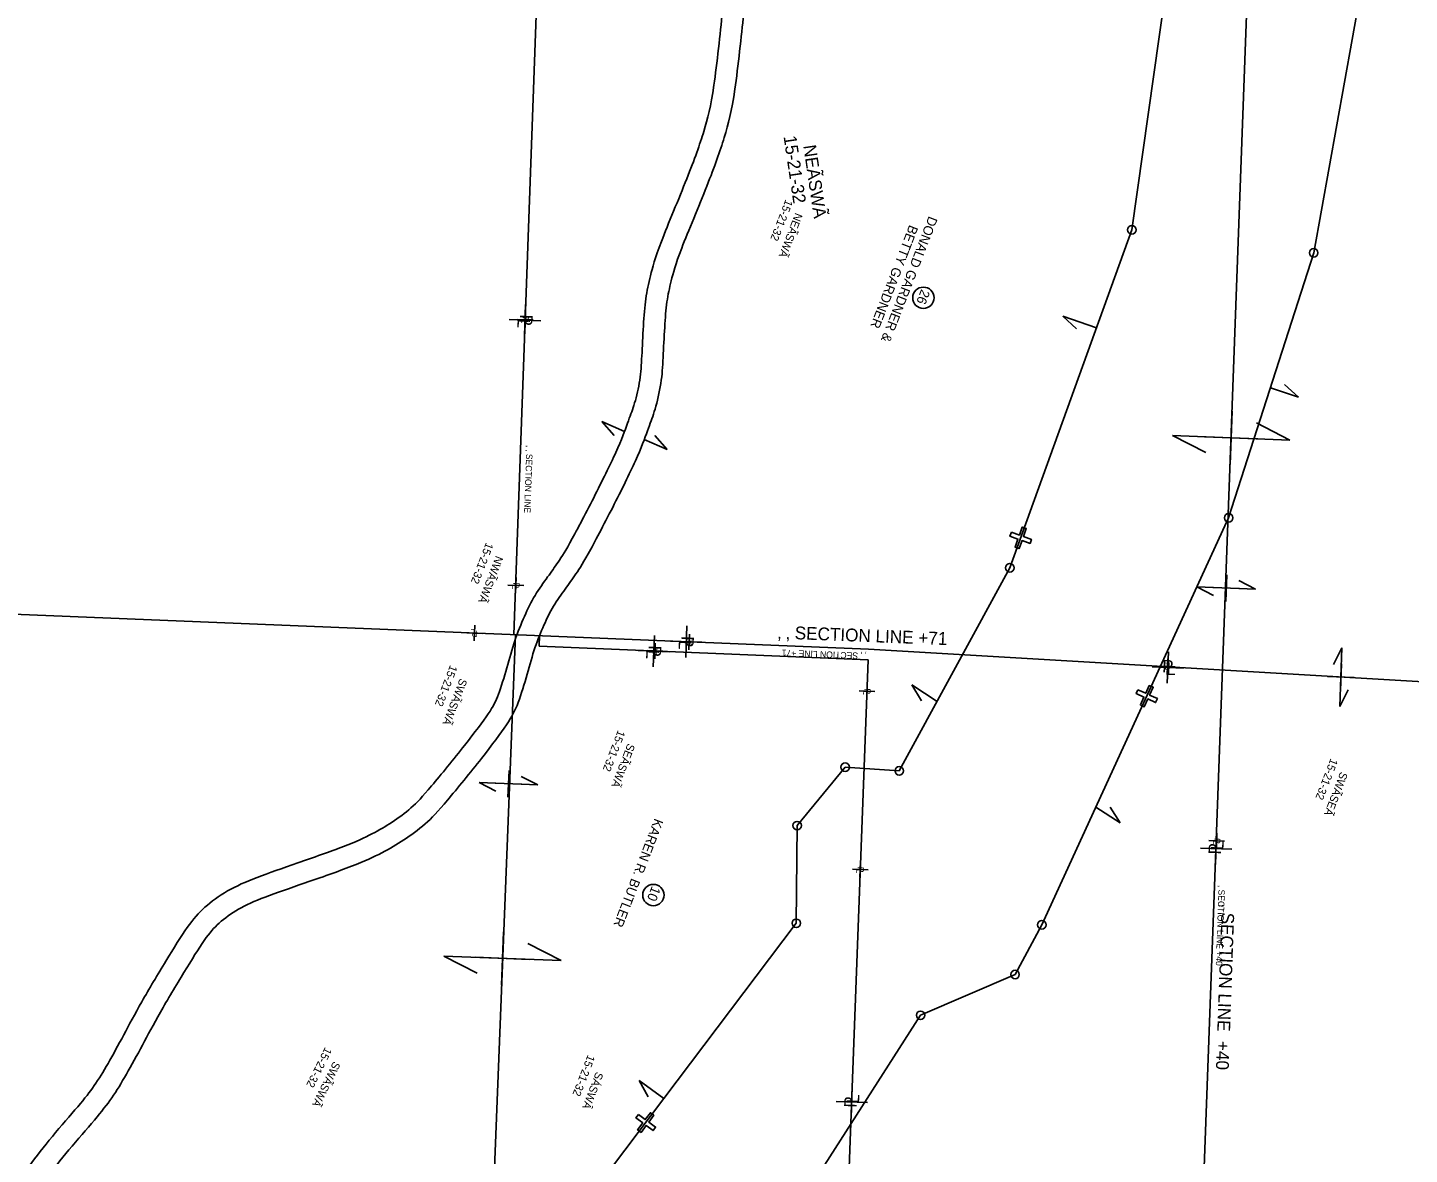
# Model space of a CAD drawing. Extents: x 2814293 to 2835768, y 121185 to 156337.
# Drawn here: x 2821316 to 2823907, y 136651 to 138763 of the extents above; entities that cross this region are included whole.
import ezdxf

# ---------------------------------------------------------------- set-up
doc = ezdxf.new("R2010")
doc.units = 0
for name, color, linetype in [('Photo-Retaining wall', 7, 'Continuous'), ('Roadway-Alignment notes', 7, 'Continuous'), ('Roadway-Ditches', 7, 'Continuous'), ('Roadway-Edge of pavement', 7, 'Continuous'), ('Roadway-Edge of shoulder', 7, 'Continuous'), ('Roadway-Entrances', 7, 'Continuous'), ('Roadway-New rw', 7, 'Continuous'), ('Roadway-Safety', 7, 'Continuous'), ('Roadway-Walls', 7, 'Continuous'), ('Scratch-2', 7, 'Continuous'), ('Scratch-5', 7, 'Continuous'), ('Text-New rw label', 7, 'Continuous'), ('Traffic_Control-Traffic barriers', 7, 'Continuous')]:
    doc.layers.add(name, color=color, linetype=linetype)

msp = doc.modelspace()

# ---------------------------------------------------------------- linework, layer by layer
at = {"layer": 'Roadway-Ditches'}
for centre in [(2822996, 138256.8), (2822489.8, 137137)]:
    msp.add_circle(centre, 20, dxfattribs=at)
at = {"layer": 'Roadway-Edge of pavement'}
for p, q in [((2822416.1, 137998.8), (2822392.8, 138025)), ((2822392.8, 138025), (2822435.6, 138006.4)), ((2822472.6, 137991), (2822515.4, 137972.4)), ((2822492.2, 137998.6), (2822515.4, 137972.4)), ((2823564.7, 137737.7), (2823562.7, 137687.7)), ((2823587.5, 137726.6), (2823618.7, 137710.6)), ((2823618.7, 137710.6), (2823508.7, 137714.8)), ((2823539.9, 137698.8), (2823508.7, 137714.8)), ((2823538.7, 137713.7), (2823588.7, 137711.7)), ((2823563.7, 137712.7), (2823563.7, 137712.7)), ((2823764.8, 137569.6), (2823780.8, 137600.7)), ((2823776.5, 137490.8), (2823780.8, 137600.7)), ((2823779.6, 137570.7), (2823777.7, 137520.7)), ((2823803.6, 137544.8), (2823753.6, 137546.7)), ((2823778.6, 137545.7), (2823778.6, 137545.7)), ((2823792.5, 137521.9), (2823776.5, 137490.8)), ((2822217.1, 137320.7), (2822219.1, 137370.7)), ((2822241.9, 137359.5), (2822273.1, 137343.5)), ((2822163.1, 137347.8), (2822273.1, 137343.5)), ((2822194.3, 137331.8), (2822163.1, 137347.8)), ((2822243.1, 137344.7), (2822193.1, 137346.6)), ((2822218.1, 137345.7), (2822218.1, 137345.7))]:
    msp.add_line(p, q, dxfattribs=at)
at = {"layer": 'Roadway-Edge of shoulder'}
for p, q in [((2822250.1, 138244.3), (2822248, 138185.4)), ((2822278.5, 138213.8), (2822219.6, 138215.9)), ((2822491.5, 137623.8), (2822489.4, 137564.9)), ((2822552.4, 137641.5), (2822550.4, 137582.6)), ((2822519.9, 137593.3), (2822461, 137595.4)), ((2822580.8, 137611), (2822522, 137613.1)), ((2823455.4, 137593.2), (2823453.3, 137534.3)), ((2823424.9, 137564.8), (2823483.8, 137562.7)), ((2823543.6, 137194.4), (2823545.6, 137253.3)), ((2823515.2, 137224.9), (2823574.1, 137222.8)), ((2822860.5, 136719.6), (2822862.5, 136778.5)), ((2822832.1, 136750.1), (2822891, 136748))]:
    msp.add_line(p, q, dxfattribs=at)
at = {"layer": 'Roadway-Entrances'}
for p, q in [((2822275.4, 138939.5), (2822227.8, 137625.4)), ((2823507.8, 136237.3), (2823605.3, 138881.7)), ((2823257.6, 138222.3), (2823320.5, 138200.6)), ((2823283.3, 138198.6), (2823257.6, 138222.3)), ((2823646.5, 138087.9), (2823699.1, 138070.8)), ((2823699.1, 138070.8), (2823673, 138094)), ((2820897, 137680), (2822893.1, 137598.2)), ((2822231.2, 137625.3), (2822073.3, 133645.3)), ((2822893.1, 137598.2), (2824874.2, 137481)), ((2823021.5, 137499.8), (2822974.1, 137530.9)), ((2822992.6, 137501.1), (2822974.1, 137530.9)), ((2823020.1, 137500.7), (2823020.1, 137500.7)), ((2823364.7, 137272.4), (2823319.3, 137302.1)), ((2823346.2, 137302.1), (2823364.7, 137272.4)), ((2822509.3, 136755.7), (2822463.2, 136789.4)), ((2822480.1, 136758.7), (2822463.2, 136789.4)), ((2822507.6, 136756.9), (2822507.6, 136756.9))]:
    msp.add_line(p, q, dxfattribs=at)
at = {"layer": 'Roadway-New rw'}
for p, q in [((2823500.4, 139189.9), (2823386.8, 138384.2)), ((2823727.7, 138341.1), (2823819.8, 138853.3)), ((2823386.8, 138384.2), (2823158, 137750.7)), ((2823568.3, 137844.4), (2823727.7, 138341.1)), ((2823218, 137081.4), (2823568.3, 137844.4)), ((2823158, 137750.7), (2822950.8, 137369.8)), ((2822849.2, 137376.9), (2822759.1, 137267.2)), ((2822950.8, 137369.8), (2822849.2, 137376.9)), ((2822759.1, 137267.2), (2822757.7, 137084.1)), ((2822757.7, 137084.1), (2822189.2, 136332.5)), ((2823167.8, 136988), (2823218, 137081.4)), ((2823167.8, 136988), (2822990.8, 136911.6))]:
    msp.add_line(p, q, dxfattribs=at)
for points in [[(2823160.9, 137817.3), (2823158.3, 137809.8), (2823173.3, 137804.4), (2823168, 137789.4), (2823175.5, 137786.7), (2823180.9, 137801.7), (2823195.9, 137796.4), (2823198.6, 137803.9), (2823183.6, 137809.3), (2823188.9, 137824.3), (2823181.4, 137827), (2823176, 137812), (2823160.9, 137817.3)], [(2823398.3, 137522), (2823395, 137514.8), (2823409.5, 137508.1), (2823402.8, 137493.6), (2823410.1, 137490.2), (2823416.8, 137504.7), (2823431.3, 137498), (2823434.6, 137505.3), (2823420.1, 137512), (2823426.8, 137526.5), (2823419.5, 137529.9), (2823412.8, 137515.3), (2823398.3, 137522)], [(2822461.7, 136725.8), (2822456.9, 136719.4), (2822469.7, 136709.8), (2822460.2, 136697), (2822466.6, 136692.2), (2822476.1, 136705), (2822489, 136695.5), (2822493.8, 136701.9), (2822480.9, 136711.4), (2822490.5, 136724.3), (2822484.1, 136729), (2822474.5, 136716.2), (2822461.7, 136725.8)]]:
    msp.add_lwpolyline(points, close=True, dxfattribs=at)
msp.add_lwpolyline([(2822670.7, 136411.7), (2822990.8, 136911.6)], dxfattribs=at)
at = {"layer": 'Roadway-Walls'}
for p, q in [((2822264.2, 138215.4), (2822234.8, 138216.4)), ((2822250, 138230.6), (2822249, 138201.2)), ((2822232.3, 137732.5), (2822231.2, 137703)), ((2822246.5, 137717.2), (2822217, 137718.3)), ((2822153.9, 137613.5), (2822154.9, 137642.9)), ((2822169.1, 137627.7), (2822139.7, 137628.7)), ((2822556.3, 137597), (2822557.4, 137626.4)), ((2822507.4, 137594.2), (2822478, 137595.3)), ((2822492.2, 137580), (2822493.2, 137609.5)), ((2822571.6, 137611.2), (2822542.1, 137612.2)), ((2823468.2, 137564.9), (2823438.7, 137566)), ((2823452.9, 137550.7), (2823454, 137580.2)), ((2822904.9, 137518.7), (2822875.4, 137519.7)), ((2822890.7, 137533.9), (2822889.6, 137504.5)), ((2823560.5, 137238.1), (2823531.1, 137239.1)), ((2823546.3, 137253.3), (2823545.3, 137223.9)), ((2822892.2, 137184.3), (2822862.8, 137185.3)), ((2822878.1, 137199.5), (2822877, 137170.1))]:
    msp.add_line(p, q, dxfattribs=at)
at = {"layer": 'Scratch-2'}
for p, q in [((2823574.8, 138044.3), (2823570.9, 137944.4)), ((2823620.5, 138022.1), (2823682.8, 137990.1)), ((2823682.8, 137990.1), (2823462.9, 137998.6)), ((2823525.2, 137966.6), (2823462.9, 137998.6)), ((2823522.9, 137996.3), (2823622.8, 137992.4)), ((2823572.9, 137994.3), (2823572.9, 137994.3)), ((2822208.6, 137068.4), (2822204.7, 136968.4)), ((2822316.6, 137014.2), (2822096.7, 137022.7)), ((2822159, 136990.7), (2822096.7, 137022.7)), ((2822254.3, 137046.2), (2822316.6, 137014.2)), ((2822156.7, 137020.4), (2822256.6, 137016.5)), ((2822206.7, 137018.4), (2822206.7, 137018.4))]:
    msp.add_line(p, q, dxfattribs=at)
at = {"layer": 'Text-New rw label'}
for centre in [(2823386.8, 138384.2), (2823727.7, 138341.1), (2823568.3, 137844.4), (2823158, 137750.7), (2822849.2, 137376.9), (2822950.8, 137369.8), (2822759.1, 137267.2), (2822757.7, 137084.1), (2823218, 137081.4), (2823167.8, 136988), (2822990.8, 136911.6)]:
    msp.add_circle(centre, 8, dxfattribs=at)
at = {"layer": 'Traffic_Control-Traffic barriers'}
for p, q in [((2822276.1, 137623.5), (2822275.3, 137603.5)), ((2822275.3, 137603.5), (2822892.3, 137578.2)), ((2822892.3, 137578.2), (2822843.3, 136268.6))]:
    msp.add_line(p, q, dxfattribs=at)
for points in [[(2820421.9, 132323.7), (2820430.3, 132339.5), (2820446.6, 132365.4), (2820477.5, 132409.8), (2820521.7, 132462.2), (2820581.9, 132544.8), (2820633.7, 132622.6), (2820678.7, 132698.5), (2820711.5, 132765.4), (2820823.8, 132974.3), (2820869.5, 133062.1), (2820906.1, 133146.6), (2820945.5, 133258.7), (2820956.4, 133356.9), (2820952.7, 133425), (2820927.9, 133503.2), (2820893.9, 133557.3), (2820809, 133702.5), (2820771.2, 133774.3), (2820745.5, 133846.6), (2820736.3, 133904.7), (2820741, 133953.4), (2820747.2, 134000.7), (2820776.6, 134101.6), (2820833.7, 134304.6), (2820904.5, 134550.3), (2820921.6, 134614.4), (2820930.5, 134682.7), (2820930.5, 134758), (2820923.8, 134863.3), (2820917.2, 134986), (2820914.2, 135053.6), (2820915.6, 135096.1), (2820930, 135192), (2820948.1, 135310.8), (2820956, 135344.7), (2820980.6, 135392.4), (2821001.2, 135416.1), (2821028.4, 135446.7), (2821056.8, 135477.7), (2821080.7, 135513.2), (2821109.6, 135587.8), (2821118.7, 135642.2), (2821136.4, 135738.5), (2821159.1, 135874.6), (2821198.2, 136048.3), (2821218.1, 136218.9), (2821227.9, 136304.7), (2821244.8, 136389.4), (2821276, 136485.3), (2821314.1, 136552.1), (2821350.9, 136605.8), (2821391.6, 136657.6), (2821445.7, 136719.4), (2821474.7, 136755.9), (2821500.8, 136798.9), (2821531.8, 136855.4), (2821562.3, 136913.6), (2821611.3, 136995.1), (2821650.2, 137057.9), (2821673.5, 137084.5), (2821709.9, 137111.3), (2821757.5, 137132.5), (2821832.5, 137158.2), (2821931.7, 137192.9), (2821982.6, 137216.4), (2822021.4, 137239.3), (2822062.8, 137269.2), (2822096.8, 137305.8), (2822172, 137398.1), (2822219.2, 137461.1), (2822236.1, 137494), (2822253.7, 137552.5), (2822267, 137602), (2822284.6, 137644.3), (2822301.1, 137678.7), (2822325.1, 137711.8), (2822343.7, 137737.3), (2822366.9, 137773.8), (2822421.5, 137879), (2822464.2, 137966.1), (2822481.4, 138016.2), (2822492.6, 138043.8), (2822505.3, 138098.1), (2822507.9, 138141.9), (2822510.7, 138203.4), (2822514.5, 138251), (2822522.5, 138286.8), (2822534.9, 138334.4), (2822594.9, 138475.5), (2822624.6, 138559.6), (2822642.4, 138629.9), (2822654.8, 138749.4), (2822658.9, 138787.6)], [(2820745, 134137.3), (2820759.2, 134187.4), (2820796.5, 134319.8), (2820866, 134561), (2820882.3, 134622.2), (2820890.5, 134685.3), (2820890.5, 134756.7), (2820883.9, 134860.9), (2820877.2, 134984), (2820874.1, 135053.3), (2820875.7, 135099.8), (2820890.4, 135198), (2820908.8, 135318.4), (2820918.2, 135358.7), (2820947.2, 135415), (2820971.2, 135442.6), (2820998.7, 135473.5), (2821025.3, 135502.5), (2821045.1, 135531.8), (2821070.8, 135598.4), (2821079.3, 135649.1), (2821097, 135745.4), (2821119.8, 135882.3), (2821158.7, 136055), (2821178.4, 136223.5), (2821188.3, 136310.9), (2821206, 136399.5), (2821239.2, 136501.5), (2821280.2, 136573.3), (2821318.6, 136629.4), (2821360.8, 136683.1), (2821415, 136745), (2821441.8, 136778.8), (2821466.2, 136818.9), (2821496.5, 136874.2), (2821527.4, 136933.2), (2821577.1, 137015.9), (2821617.9, 137081.8), (2821646.4, 137114.1), (2821689.7, 137146.1), (2821742.9, 137169.7), (2821819.5, 137196), (2821916.7, 137230), (2821964, 137251.9), (2821999.5, 137272.8), (2822036.2, 137299.3), (2822066.7, 137332.1), (2822140.5, 137422.7), (2822185.2, 137482.3), (2822198.9, 137509), (2822215.2, 137563.4), (2822229.1, 137614.9), (2822248, 137660.6), (2822266.7, 137699.3), (2822292.7, 137735.3), (2822310.6, 137759.8), (2822332.2, 137793.7), (2822385.8, 137897), (2822427.2, 137981.4), (2822444, 138030.2), (2822454.4, 138055.9), (2822465.5, 138103.9), (2822468, 138144.1), (2822470.8, 138205.9), (2822474.8, 138257), (2822483.6, 138296.3), (2822497, 138347.3), (2822557.6, 138490), (2822586.2, 138571.2), (2822602.9, 138636.9), (2822615, 138753.6), (2822619.1, 138791.9)]]:
    msp.add_open_spline(points, degree=3, dxfattribs=at)

# ---------------------------------------------------------------- texts
at = {"layer": 'Photo-Retaining wall'}
for s, rotation, p in [('15-21-32', 248.849, (2822737.7, 138442)), ('NEÃSWÃ', 248.849, (2822756, 138417.1)), ('15-21-32', 248.849, (2822176.2, 137799)), ('NWÃSWÃ', 248.849, (2822194.5, 137774.2)), ('15-21-32', 248.849, (2822108.8, 137569.2)), ('SWÃSWÃ', 248.849, (2822127.1, 137544.3)), ('15-21-32', 248.849, (2822423.4, 137447.2)), ('SEÃSWÃ', 248.849, (2822441.7, 137422.4)), ('15-21-32', 248.849, (2823759.7, 137394.1)), ('SWÃSEÃ', 248.849, (2823778, 137369.2)), ('15-21-32', 243.5041, (2821874.2, 136852.8)), ('SWÃSWÃ', 243.5041, (2821890.1, 136826.3)), ('15-21-32', 248.849, (2822366.8, 136838.5)), ('SÁSWÂ', 248.849, (2822382.3, 136806.7))]:
    msp.add_text(s, height=15, rotation=rotation, dxfattribs=at).set_placement(p)
at = {"layer": 'Roadway-Alignment notes'}
for s, p in [('15-21-32', (2822733.7, 138559.2)), ('NEÃSWÃ', (2822770.6, 138541.9))]:
    msp.add_text(s, height=24, rotation=278.3561, dxfattribs=at).set_placement(p)
at = {"layer": 'Roadway-Ditches'}
for s, p in [('DONALD GARDNER &', (2823006.2, 138411)), ('BETTY GARDNER', (2822969.8, 138394.6)), ('26', (2822992.1, 138273.9)), ('KAREN R. BUTLER', (2822492.1, 137281.9)), ('10', (2822487.1, 137154.9))]:
    msp.add_text(s, height=18, rotation=248.849, dxfattribs=at).set_placement(p)
at = {"layer": 'Roadway-Edge of shoulder'}
for s, rotation, p in [('L', 267.9775, (2822235.2, 138218)), ('P', 267.9775, (2822239.8, 138225.9)), ('P', 267.9775, (2822542.2, 137623)), ('L', 267.9775, (2822476.6, 137597.5)), ('P', 267.9775, (2822481.2, 137605.4)), ('L', 267.9775, (2822537.6, 137615.2)), ('P', 357.9775, (2823443.4, 137554.5)), ('L', 357.9775, (2823451.2, 137549.9)), ('P', 87.9775, (2823553.9, 137212.8)), ('L', 87.9775, (2823558.4, 137220.7)), ('L', 87.9775, (2822875.3, 136745.9)), ('P', 87.9775, (2822870.8, 136738.1))]:
    msp.add_text(s, height=23.6, rotation=rotation, dxfattribs=at).set_placement(p)
at = {"layer": 'Roadway-Safety'}
for s, rotation, p in [('‚ ‚ SECTION LINE', 267.9775, (2822251.7, 137980.5)), ('‚ ‚ SECTION LINE +71', 177.7804, (2822889.7, 137591)), ('‚ SECTION LINE +40', 267.99, (2823549.5, 137155.6))]:
    msp.add_text(s, height=12, rotation=rotation, dxfattribs=at).set_placement(p)
at = {"layer": 'Roadway-Walls'}
for s, rotation, p in [('L', 267.9775, (2822242.6, 138217.5)), ('P', 267.9775, (2822244.9, 138221.4)), ('P', 267.9775, (2822227.1, 137723.3)), ('L', 267.9775, (2822224.8, 137719.4)), ('L', 177.9775, (2822156, 137635.1)), ('P', 177.9775, (2822159.9, 137632.8)), ('L', 177.9775, (2822558.4, 137618.6)), ('P', 177.9775, (2822562.4, 137616.3)), ('L', 177.9775, (2822494.3, 137601.7)), ('P', 177.9775, (2822498.2, 137599.4)), ('L', 177.9775, (2823455, 137572.4)), ('P', 177.9775, (2823459, 137570.1)), ('L', 267.9775, (2822883.2, 137520.8)), ('P', 267.9775, (2822885.5, 137524.7)), ('L', 267.9775, (2823538.9, 137240.2)), ('P', 267.9775, (2823541.2, 137244.1)), ('L', 267.9775, (2822870.6, 137186.4)), ('P', 267.9775, (2822872.9, 137190.3))]:
    msp.add_text(s, height=11.8, rotation=rotation, dxfattribs=at).set_placement(p)
at = {"layer": 'Scratch-5'}
for s, rotation, p in [('‚ ‚ SECTION LINE +71', 357.7804, (2822722.3, 137618)), ('‚ SECTION LINE  +40', 267.99, (2823555.3, 137120.5))]:
    msp.add_text(s, height=24, rotation=rotation, dxfattribs=at).set_placement(p)

doc.saveas('drawing.dxf')
